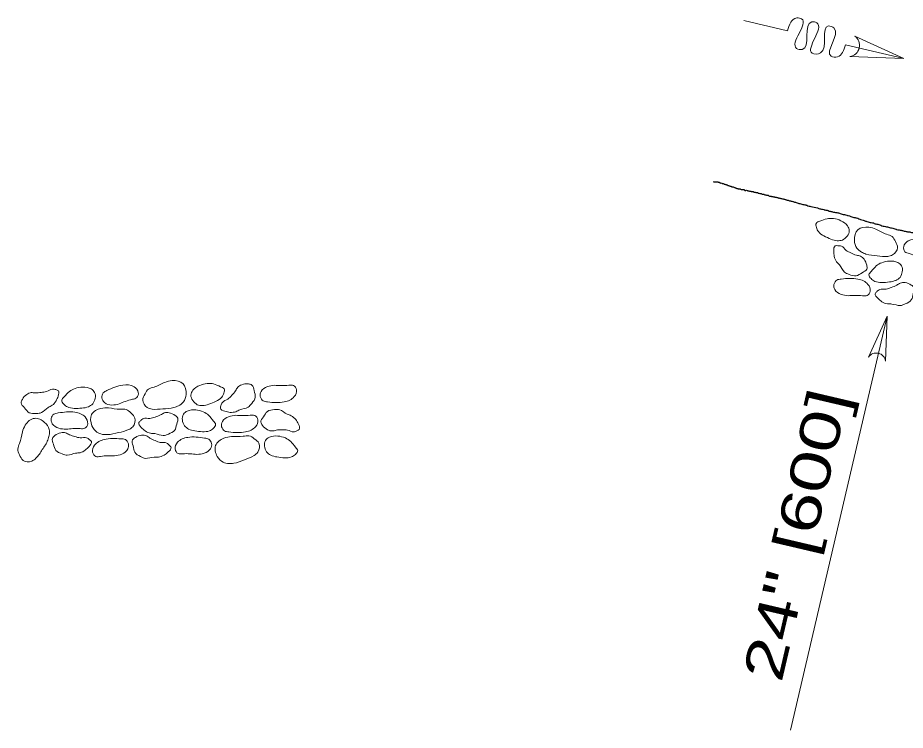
# Model space of a CAD drawing. Extents: x 1043.1 to 1101.1, y 672.4 to 716.4.
# Drawn here: x 1091.622 to 1095.184, y 703.481 to 706.34 of the extents above; entities that cross this region are included whole.
import ezdxf
from ezdxf.enums import TextEntityAlignment as Align

# ---------------------------------------------------------------- set-up
doc = ezdxf.new("R2010")
doc.units = 0
doc.header["$LTSCALE"] = 0.064
doc.layers.add('1', color=7, linetype='Continuous', lineweight=13)

msp = doc.modelspace()

# ---------------------------------------------------------------- linework, layer by layer
at = {"layer": '1'}
for p, q in [((1094.71092, 706.28667), (1094.53583, 706.32817)), ((1095.17767, 706.17592), (1094.94433, 706.23133)), ((1095.111, 705.14192), (1094.72358, 703.4805))]:
    msp.add_line(p, q, dxfattribs=at)
for points in [[(1094.98133, 706.26617), (1095.17767, 706.17592), (1094.96175, 706.18367), (1094.96175, 706.18383)], [(1095.03658, 704.978), (1095.111, 705.14192), (1095.10533, 704.962), (1095.10525, 704.962)]]:
    msp.add_lwpolyline(points, dxfattribs=at)
for centre, radius, start, end in [((1094.95479, 706.22895), 0.04573, 278.74184, 54.56797), ((1095.06763, 704.95606), 0.03811, 8.96195, 144.78808)]:
    msp.add_arc(centre, radius, start, end, dxfattribs=at)
for points in [[(1094.94433, 706.23133), (1094.91175, 706.18275), (1094.8865, 706.18533), (1094.898, 706.29875), (1094.87617, 706.30667), (1094.84342, 706.19825), (1094.8105, 706.19775), (1094.82883, 706.31925), (1094.80883, 706.32325), (1094.7705, 706.212), (1094.748, 706.21675), (1094.76825, 706.33492), (1094.74842, 706.33883), (1094.71092, 706.28667)], [(1094.93217, 705.447), (1094.91133, 705.44467), (1094.88575, 705.45133), (1094.8575, 705.46417), (1094.83533, 705.48133), (1094.82717, 705.498), (1094.82717, 705.5155), (1094.84175, 705.52317), (1094.87025, 705.53325), (1094.89575, 705.53392), (1094.92567, 705.52525), (1094.95233, 705.50417), (1094.95917, 705.48517), (1094.95092, 705.46317), (1094.93217, 705.447)], [(1095.00775, 705.39942), (1094.99, 705.41475), (1094.97983, 705.44642), (1094.99325, 705.48842), (1095.03733, 705.49942), (1095.06642, 705.49117), (1095.109, 705.47083), (1095.13083, 705.462), (1095.14467, 705.44175), (1095.15275, 705.41675), (1095.133, 705.38767), (1095.11342, 705.38192), (1095.07067, 705.38433), (1095.02642, 705.3915), (1095.00775, 705.39942)], [(1095.25283, 705.37242), (1095.28183, 705.36675), (1095.31217, 705.37567), (1095.32292, 705.39375), (1095.31825, 705.41392), (1095.30375, 705.42417), (1095.241, 705.44883), (1095.19592, 705.44383), (1095.17783, 705.4215), (1095.18275, 705.40067), (1095.20017, 705.39317), (1095.25283, 705.37242)], [(1094.89875, 705.38225), (1094.897, 705.4035), (1094.90283, 705.424), (1094.91342, 705.425), (1094.92767, 705.42325), (1094.94683, 705.40625), (1094.96583, 705.39617), (1094.98783, 705.387), (1095.004, 705.38292), (1095.01875, 705.37067), (1095.02942, 705.34625), (1095.02967, 705.33133), (1095.01067, 705.31633), (1094.987, 705.30375), (1094.95875, 705.30975), (1094.93983, 705.31933), (1094.9205, 705.34767), (1094.90817, 705.3605), (1094.89875, 705.38225)], [(1095.16325, 705.29767), (1095.14617, 705.28567), (1095.12042, 705.27933), (1095.0895, 705.27717), (1095.06183, 705.28175), (1095.04667, 705.29267), (1095.03833, 705.308), (1095.0475, 705.3215), (1095.06783, 705.34392), (1095.08992, 705.35675), (1095.12033, 705.36333), (1095.15383, 705.35742), (1095.16883, 705.344), (1095.17217, 705.32067), (1095.16325, 705.29767)], [(1094.95525, 705.22425), (1094.92625, 705.22967), (1094.90133, 705.249), (1094.89792, 705.26983), (1094.90975, 705.28683), (1094.92692, 705.291), (1094.99425, 705.291), (1095.03433, 705.26983), (1095.043, 705.24242), (1095.03083, 705.22483), (1095.01183, 705.22425), (1094.95525, 705.22425)], [(1095.09033, 705.19992), (1095.074, 705.21375), (1095.0635, 705.23233), (1095.07033, 705.2405), (1095.08167, 705.24933), (1095.10725, 705.25092), (1095.12792, 705.25733), (1095.14983, 705.26642), (1095.16417, 705.275), (1095.18325, 705.27675), (1095.208, 705.26717), (1095.21875, 705.25675), (1095.216, 705.23267), (1095.20825, 705.207), (1095.184, 705.19125), (1095.16375, 705.18467), (1095.13017, 705.19092), (1095.11225, 705.19125), (1095.09033, 705.19992)], [(1092.02933, 704.78983), (1092.00008, 704.78542), (1091.97025, 704.7955), (1091.96017, 704.81392), (1091.96558, 704.83392), (1091.98058, 704.84358), (1092.04408, 704.86575), (1092.089, 704.859), (1092.10608, 704.83592), (1092.10042, 704.81525), (1092.08267, 704.8085), (1092.02933, 704.78983)], [(1092.268, 704.78233), (1092.28633, 704.79692), (1092.29775, 704.82808), (1092.286, 704.87067), (1092.24233, 704.8835), (1092.213, 704.87633), (1092.16967, 704.85758), (1092.14767, 704.84983), (1092.13308, 704.83008), (1092.124, 704.80533), (1092.14242, 704.7755), (1092.16183, 704.769), (1092.20467, 704.76983), (1092.249, 704.77525), (1092.268, 704.78233)], [(1092.34283, 704.7865), (1092.36358, 704.78333), (1092.38942, 704.789), (1092.41817, 704.80058), (1092.44092, 704.81683), (1092.44967, 704.83342), (1092.4505, 704.85075), (1092.43617, 704.859), (1092.40817, 704.87017), (1092.38275, 704.87192), (1092.3525, 704.86442), (1092.32492, 704.8445), (1092.31733, 704.82567), (1092.32475, 704.80342), (1092.34283, 704.7865)], [(1092.47433, 704.75617), (1092.45358, 704.76092), (1092.4355, 704.77258), (1092.43792, 704.78308), (1092.44383, 704.79608), (1092.46583, 704.80933), (1092.48125, 704.8245), (1092.49633, 704.84275), (1092.50525, 704.857), (1092.52142, 704.86708), (1092.54792, 704.87017), (1092.56208, 704.86583), (1092.57092, 704.84317), (1092.57575, 704.81708), (1092.56133, 704.79167), (1092.54658, 704.77658), (1092.51375, 704.76667), (1092.49775, 704.75858), (1092.47433, 704.75617)], [(1092.65308, 704.86492), (1092.62417, 704.85942), (1092.59925, 704.83992), (1092.59583, 704.81917), (1092.60783, 704.80225), (1092.625, 704.79792), (1092.69208, 704.798), (1092.73225, 704.81917), (1092.74092, 704.84658), (1092.72883, 704.86425), (1092.70975, 704.86492), (1092.65308, 704.86492)], [(1091.77625, 704.80208), (1091.78467, 704.82167), (1091.7855, 704.843), (1091.77575, 704.84725), (1091.76175, 704.84983), (1091.73817, 704.83967), (1091.71683, 704.83608), (1091.69317, 704.83417), (1091.6765, 704.83542), (1091.65867, 704.82808), (1091.64092, 704.80833), (1091.63608, 704.79433), (1091.6495, 704.774), (1091.668, 704.75475), (1091.69675, 704.75175), (1091.71783, 704.755), (1091.745, 704.776), (1091.76083, 704.78433), (1091.77625, 704.80208)], [(1091.9235, 704.78975), (1091.90592, 704.7785), (1091.87992, 704.77325), (1091.849, 704.77225), (1091.8215, 704.77792), (1091.80683, 704.78942), (1091.79917, 704.80508), (1091.80883, 704.81842), (1091.82992, 704.84), (1091.8525, 704.85175), (1091.88317, 704.85733), (1091.9165, 704.85008), (1091.93092, 704.83608), (1091.93333, 704.8125), (1091.9235, 704.78975)], [(1091.81625, 704.68833), (1091.787, 704.69242), (1091.76117, 704.71067), (1091.75683, 704.73125), (1091.76783, 704.74883), (1091.78483, 704.75375), (1091.852, 704.75692), (1091.893, 704.7375), (1091.903, 704.71067), (1091.89158, 704.6925), (1091.87267, 704.691), (1091.81625, 704.68833)], [(1091.96217, 704.66783), (1091.94042, 704.67633), (1091.92017, 704.70267), (1091.91867, 704.74692), (1091.95642, 704.772), (1091.98675, 704.77392), (1092.03375, 704.769), (1092.05717, 704.76792), (1092.07692, 704.7535), (1092.09275, 704.73275), (1092.08408, 704.69867), (1092.0675, 704.68667), (1092.0265, 704.67467), (1091.9825, 704.66667), (1091.96217, 704.66783)], [(1092.291, 704.70183), (1092.30775, 704.68908), (1092.33308, 704.68175), (1092.36392, 704.67833), (1092.39183, 704.68183), (1092.40733, 704.69217), (1092.41633, 704.70725), (1092.40767, 704.72117), (1092.38833, 704.74433), (1092.36667, 704.75808), (1092.3365, 704.76583), (1092.30283, 704.76133), (1092.28725, 704.7485), (1092.283, 704.72525), (1092.291, 704.70183)], [(1092.73783, 704.72717), (1092.74858, 704.70875), (1092.75217, 704.68775), (1092.74292, 704.68217), (1092.72933, 704.67783), (1092.70467, 704.68483), (1092.68317, 704.68592), (1092.65942, 704.68458), (1092.643, 704.68133), (1092.62458, 704.68617), (1092.6045, 704.70367), (1092.59783, 704.71692), (1092.60858, 704.73867), (1092.62442, 704.76017), (1092.65258, 704.76692), (1092.67375, 704.76633), (1092.70342, 704.749), (1092.72017, 704.74275), (1092.73783, 704.72717)], [(1091.74892, 704.6645), (1091.74833, 704.68792), (1091.73033, 704.71592), (1091.68917, 704.73208), (1091.65283, 704.70508), (1091.641, 704.67733), (1091.62958, 704.63133), (1091.62267, 704.60892), (1091.62967, 704.58542), (1091.64392, 704.56342), (1091.67875, 704.56017), (1091.69558, 704.57175), (1091.72092, 704.6065), (1091.74325, 704.64517), (1091.74892, 704.6645)], [(1092.13367, 704.68158), (1092.11783, 704.696), (1092.10817, 704.715), (1092.11525, 704.72283), (1092.12692, 704.73125), (1092.15258, 704.73183), (1092.1735, 704.73733), (1092.19567, 704.74567), (1092.21042, 704.75375), (1092.22958, 704.75458), (1092.25408, 704.744), (1092.26417, 704.73325), (1092.2605, 704.70925), (1092.25175, 704.68392), (1092.227, 704.66908), (1092.2065, 704.66333), (1092.17308, 704.671), (1092.15517, 704.672), (1092.13367, 704.68158)], [(1092.49783, 704.74425), (1092.46875, 704.73875), (1092.44392, 704.71933), (1092.44042, 704.69858), (1092.45242, 704.68158), (1092.46958, 704.67742), (1092.53667, 704.6775), (1092.57692, 704.69858), (1092.58567, 704.726), (1092.57342, 704.74367), (1092.5545, 704.74425), (1092.49783, 704.74425)], [(1091.8935, 704.60442), (1091.90875, 704.61933), (1091.91792, 704.63858), (1091.91058, 704.64625), (1091.89875, 704.65425), (1091.87317, 704.65408), (1091.852, 704.659), (1091.82958, 704.66658), (1091.81467, 704.674), (1091.79542, 704.67433), (1091.77142, 704.66308), (1091.7615, 704.652), (1091.76583, 704.62808), (1091.77533, 704.60317), (1091.80067, 704.58917), (1091.82133, 704.584), (1091.8545, 704.59258), (1091.87225, 704.59408), (1091.8935, 704.60442)], [(1092.01133, 704.582), (1092.04025, 704.58875), (1092.06417, 704.60933), (1092.06667, 704.63025), (1092.05417, 704.64675), (1092.03667, 704.65008), (1091.96933, 704.64692), (1091.93033, 704.624), (1091.92292, 704.59625), (1091.93583, 704.57925), (1091.95483, 704.57942), (1092.01133, 704.582)], [(1092.20933, 704.58408), (1092.22625, 704.59717), (1092.2375, 704.61517), (1092.23108, 704.62367), (1092.22017, 704.63292), (1092.19458, 704.63558), (1092.17425, 704.64275), (1092.15267, 704.65275), (1092.13867, 704.66192), (1092.11958, 704.66433), (1092.09442, 704.65575), (1092.08325, 704.64583), (1092.08508, 704.62158), (1092.09192, 704.59583), (1092.11542, 704.57892), (1092.13533, 704.57158), (1092.16933, 704.57658), (1092.18717, 704.57617), (1092.20933, 704.58408)], [(1092.34117, 704.58758), (1092.37033, 704.59183), (1092.39608, 704.61025), (1092.40025, 704.63092), (1092.38917, 704.64833), (1092.37217, 704.65317), (1092.30483, 704.65575), (1092.264, 704.63625), (1092.25417, 704.60925), (1092.26567, 704.59117), (1092.28467, 704.58983), (1092.34117, 704.58758)], [(1092.46942, 704.55025), (1092.44675, 704.55575), (1092.42317, 704.57925), (1092.416, 704.62275), (1092.45008, 704.65275), (1092.47967, 704.65867), (1092.52692, 704.66), (1092.55033, 704.66217), (1092.57175, 704.6505), (1092.59033, 704.63192), (1092.58617, 704.59692), (1092.57133, 704.58292), (1092.53217, 704.56558), (1092.48975, 704.55175), (1092.46942, 704.55025)], [(1092.62067, 704.59717), (1092.63742, 704.5845), (1092.66275, 704.57708), (1092.69358, 704.57367), (1092.72133, 704.57708), (1092.73692, 704.58742), (1092.74583, 704.60242), (1092.73717, 704.61642), (1092.71783, 704.63967), (1092.69625, 704.65333), (1092.66617, 704.66108), (1092.6325, 704.65658), (1092.61692, 704.64375), (1092.61267, 704.62058), (1092.62067, 704.59717)]]:
    msp.add_spline(points, degree=3, dxfattribs=at)
at = {"layer": '1', "lineweight": 25}
for points in [[(1094.41592, 705.68142), (1094.41392, 705.68083), (1094.417, 705.68083), (1094.42167, 705.68083), (1094.42475, 705.68083), (1094.42775, 705.68083), (1094.43233, 705.68083), (1094.43392, 705.67933), (1094.437, 705.67933), (1094.44, 705.67775), (1094.44317, 705.67625), (1094.44775, 705.67625), (1094.44933, 705.67475), (1094.45233, 705.67475), (1094.45542, 705.67317), (1094.46, 705.67167), (1094.46467, 705.67), (1094.46933, 705.6685), (1094.47233, 705.667), (1094.477, 705.66542), (1094.48167, 705.66392), (1094.48625, 705.66233), (1094.48775, 705.66083), (1094.49083, 705.66083), (1094.49542, 705.65933), (1094.4985, 705.65775), (1094.50167, 705.65775), (1094.50467, 705.65625), (1094.50775, 705.65467), (1094.51233, 705.65467), (1094.51392, 705.65317), (1094.5185, 705.65317), (1094.52317, 705.65175), (1094.52775, 705.65017), (1094.53233, 705.65017), (1094.5385, 705.64867), (1094.54, 705.647), (1094.54467, 705.647), (1094.54925, 705.647), (1094.55225, 705.64542), (1094.55533, 705.64542), (1094.55842, 705.644), (1094.5615, 705.644), (1094.56617, 705.64242), (1094.57225, 705.64242), (1094.57533, 705.64092), (1094.57842, 705.63933), (1094.58142, 705.63933), (1094.58617, 705.63783), (1094.59075, 705.63783), (1094.59383, 705.63633), (1094.59992, 705.63475), (1094.6045, 705.63475), (1094.60767, 705.63325), (1094.61075, 705.63167), (1094.61533, 705.63167), (1094.61842, 705.63017), (1094.62142, 705.62867), (1094.6245, 705.62867), (1094.62917, 705.627), (1094.63375, 705.627), (1094.63683, 705.6255), (1094.643, 705.62392), (1094.64617, 705.62392), (1094.64767, 705.62242), (1094.65075, 705.62242), (1094.65533, 705.62083), (1094.65992, 705.62083), (1094.66142, 705.61933), (1094.666, 705.61933), (1094.67075, 705.61783), (1094.67683, 705.61625), (1094.67992, 705.61625), (1094.6845, 705.61475), (1094.69075, 705.61317), (1094.69683, 705.61167), (1094.703, 705.61017), (1094.70767, 705.6085), (1094.71375, 705.607), (1094.71992, 705.60542), (1094.726, 705.60392), (1094.73225, 705.60242), (1094.73683, 705.60083), (1094.743, 705.59933), (1094.75067, 705.59625), (1094.75683, 705.59475), (1094.76133, 705.59475), (1094.769, 705.59167), (1094.77675, 705.59), (1094.78442, 705.5885), (1094.789, 705.587)], [(1094.789, 705.587), (1094.79825, 705.58392), (1094.80442, 705.58233), (1094.83217, 705.57625), (1094.84133, 705.57317), (1094.8475, 705.57167), (1094.85675, 705.57), (1094.86133, 705.5685), (1094.8705, 705.56692), (1094.87825, 705.56392), (1094.88592, 705.56233), (1094.89217, 705.56083), (1094.89983, 705.55925), (1094.909, 705.55775), (1094.91675, 705.55617), (1094.92283, 705.55467), (1094.9305, 705.5515), (1094.93975, 705.55), (1094.949, 705.54692), (1094.955, 705.54542), (1094.96583, 705.54233), (1094.9735, 705.53925), (1094.98275, 705.53775), (1094.98892, 705.53617), (1094.99817, 705.533), (1095.00425, 705.53), (1095.015, 705.52692), (1095.02425, 705.52383), (1095.03042, 705.52233), (1095.03967, 705.51925), (1095.04733, 705.51767), (1095.0565, 705.51617), (1095.06275, 705.513), (1095.07042, 705.5115), (1095.07817, 705.50992), (1095.08583, 705.50692), (1095.095, 705.50383), (1095.09967, 705.50383), (1095.10883, 705.50075), (1095.1165, 705.49917), (1095.12425, 705.49617), (1095.12883, 705.49617), (1095.13817, 705.4945), (1095.14583, 705.49142), (1095.14883, 705.48992), (1095.15967, 705.48842), (1095.16725, 705.48683), (1095.17333, 705.48533), (1095.1795, 705.48383), (1095.18725, 705.48225), (1095.19333, 705.48075), (1095.1995, 705.48075), (1095.20567, 705.47925), (1095.21333, 705.47775), (1095.2195, 705.47617), (1095.22725, 705.47467), (1095.23492, 705.47317), (1095.24267, 705.47317), (1095.24725, 705.4715), (1095.25492, 705.47), (1095.26267, 705.47), (1095.27025, 705.46842), (1095.27642, 705.46692), (1095.28267, 705.46542), (1095.28875, 705.46542), (1095.29333, 705.46542), (1095.2995, 705.46383), (1095.30417, 705.46233), (1095.31025, 705.46233), (1095.31333, 705.46233), (1095.31792, 705.46075), (1095.321, 705.46075), (1095.32567, 705.45925), (1095.33025, 705.45775), (1095.33333, 705.45775), (1095.33642, 705.45617), (1095.3395, 705.45617), (1095.34417, 705.45467), (1095.34725, 705.45467), (1095.35333, 705.453), (1095.35642, 705.4515), (1095.361, 705.4515), (1095.364, 705.45), (1095.37017, 705.44842), (1095.37633, 705.44692), (1095.38092, 705.44692), (1095.3855, 705.44533), (1095.38867, 705.44533), (1095.39325, 705.44383), (1095.39783, 705.44233), (1095.404, 705.44233)]]:
    msp.add_spline(points, degree=3, dxfattribs=at)

# ---------------------------------------------------------------- texts
at = {"layer": '1', "width": 1.4}
msp.add_text('24" [600]', height=0.16, rotation=76.8, dxfattribs=at).set_placement((1094.82244, 704.24615), align=Align.CENTER)

doc.saveas('drawing.dxf')
